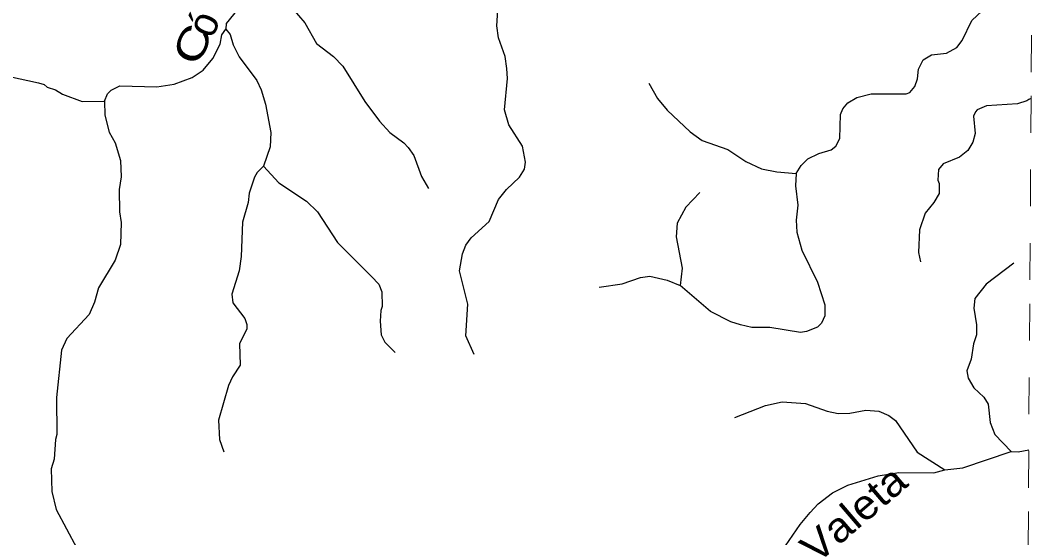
# Model space of a CAD drawing. Extents: x 577 to 602.9, y 7483.8 to 7511.6.
# Drawn here: x 600.095 to 602.863, y 7506.798 to 7508.204 of the extents above; entities that cross this region are included whole.
import ezdxf
from ezdxf.enums import TextEntityAlignment as Align

# ---------------------------------------------------------------- set-up
doc = ezdxf.new("R2010")
doc.units = 0
doc.header["$LTSCALE"] = 0.032
doc.linetypes.add('SHORT_DASHED', pattern=[2.7, 1.5, -1.2])
doc.layers.add('53', color=7, linetype='SHORT_DASHED', lineweight=13)
doc.layers.add('7', color=7, linetype='Continuous', lineweight=25)
doc.layers.add('61', color=7, linetype='Continuous')

msp = doc.modelspace()

# ---------------------------------------------------------------- linework, layer by layer
at = {"layer": '53'}
msp.add_lwpolyline([(602.7836, 7499.5909), (602.7874, 7500.1558), (602.7912, 7500.7206), (602.795, 7501.2855), (602.7988, 7501.8503), (602.8025, 7502.4151), (602.8063, 7502.98), (602.8101, 7503.5448), (602.8139, 7504.1096), (602.8177, 7504.6745), (602.8215, 7505.2393), (602.8253, 7505.8041), (602.829, 7506.369), (602.8328, 7506.9338), (602.8366, 7507.4986), (602.8404, 7508.0635), (602.8441, 7508.6283), (602.8479, 7509.1931), (602.8517, 7509.758), (602.8555, 7510.3228), (602.8592, 7510.8876), (602.863, 7511.4524)], dxfattribs=at)
at = {"layer": '7'}
for points in [[(600.7468, 7508.3628), (600.7312, 7508.3309), (600.7173, 7508.2851), (600.6969, 7508.2484), (600.6536, 7508.1952), (600.6528, 7508.1797)], [(600.7468, 7508.3628), (600.7546, 7508.3548), (600.7607, 7508.3415), (600.7721, 7508.3064), (600.7909, 7508.2704), (600.8326, 7508.2369), (600.8677, 7508.1969), (600.8988, 7508.1413), (600.9454, 7508.1053), (600.9707, 7508.0792), (601.0304, 7507.9835), (601.0705, 7507.9296), (601.0983, 7507.8993), (601.1367, 7507.8715), (601.1481, 7507.8585), (601.1637, 7507.8364), (601.1841, 7507.78), (601.2031, 7507.7474)], [(602.2018, 7507.7873), (602.2157, 7507.8094), (602.2336, 7507.8274), (602.2631, 7507.8421), (602.2966, 7507.8519), (602.3097, 7507.8617), (602.3203, 7507.883), (602.3219, 7507.9484), (602.3285, 7507.9639), (602.3424, 7507.9794), (602.3669, 7507.9941), (602.4053, 7508.004), (602.5009, 7508.004), (602.5107, 7508.008), (602.5238, 7508.0244), (602.5312, 7508.0448), (602.5344, 7508.071), (602.5467, 7508.0963), (602.5696, 7508.1102), (602.6105, 7508.1151), (602.6383, 7508.1298), (602.653, 7508.1495), (602.6791, 7508.2034), (602.7339, 7508.2549)], [(601.327, 7507.296), (601.3051, 7507.3468), (601.31, 7507.4326), (601.2871, 7507.5233), (601.2953, 7507.5691), (601.3051, 7507.5928), (601.319, 7507.6132), (601.368, 7507.6574), (601.3933, 7507.717), (601.4154, 7507.744), (601.4506, 7507.7775), (601.4636, 7507.7996), (601.4669, 7507.8184), (601.4587, 7507.8617), (601.4211, 7507.9198), (601.4097, 7507.9606), (601.4179, 7508.0456), (601.4162, 7508.0734), (601.4113, 7508.1053), (601.3933, 7508.1568), (601.3893, 7508.1887), (601.3917, 7508.232)], [(600.3234, 7507.9843), (600.3315, 7508.004), (600.3413, 7508.0138), (600.365, 7508.026), (600.4656, 7508.0228), (600.5122, 7508.0309), (600.5612, 7508.0489), (600.5915, 7508.0685), (600.6176, 7508.1004), (600.6372, 7508.1388), (600.6421, 7508.165), (600.6528, 7508.1797)], [(600.6528, 7508.1797), (600.6642, 7508.1658), (600.6724, 7508.1372), (600.6887, 7508.1045), (600.737, 7508.0407), (600.7492, 7508.0154), (600.7607, 7507.9762), (600.7754, 7507.8993), (600.7737, 7507.8601), (600.7549, 7507.8078)], [(599.9787, 7508.0644), (600.0136, 7508.0546), (600.0651, 7508.0514), (600.1443, 7508.0342), (600.1591, 7508.0293), (600.1672, 7508.0219), (600.1901, 7508.0154), (600.2089, 7508.0031), (600.2629, 7507.9835), (600.3234, 7507.9843)], [(601.8016, 7508.0333), (601.8249, 7507.9917), (601.8519, 7507.9598), (601.914, 7507.901), (601.9467, 7507.8773), (602.0162, 7507.8527), (602.0652, 7507.82), (602.1078, 7507.8004), (602.1494, 7507.7922), (602.2018, 7507.7873)], [(600.3234, 7507.9843), (600.3242, 7507.9467), (600.3356, 7507.9001), (600.352, 7507.8707), (600.3667, 7507.8233), (600.3683, 7507.7783), (600.3634, 7507.744), (600.3642, 7507.6835), (600.3683, 7507.6549), (600.3667, 7507.5944), (600.352, 7507.5519), (600.307, 7507.4767), (600.2964, 7507.4383), (600.2817, 7507.4048), (600.2212, 7507.3394), (600.2065, 7507.3075), (600.1934, 7507.1792), (600.1942, 7507.0786), (600.1901, 7507.0648), (600.1868, 7507.0116), (600.1787, 7506.9855), (600.1803, 7506.9233), (600.1918, 7506.8743), (600.2482, 7506.7697)], [(602.8399, 7507.9918), (602.8337, 7507.9884), (602.8279, 7507.9852), (602.8026, 7507.977), (602.7184, 7507.9713), (602.6938, 7507.9606), (602.6889, 7507.9549), (602.6832, 7507.9435), (602.6881, 7507.8961), (602.6816, 7507.8732), (602.6685, 7507.8503), (602.6456, 7507.8323), (602.6007, 7507.8143), (602.5884, 7507.7988), (602.5868, 7507.7694), (602.59, 7507.7604), (602.59, 7507.7334), (602.5761, 7507.7089), (602.5524, 7507.6803), (602.5369, 7507.6345), (602.5344, 7507.5732), (602.5392, 7507.5475)], [(600.7549, 7507.8078), (600.7378, 7507.7906), (600.7304, 7507.7775), (600.7165, 7507.7342), (600.7133, 7507.7089), (600.6985, 7507.6557), (600.6945, 7507.5626), (600.6887, 7507.5233), (600.6691, 7507.4596), (600.6716, 7507.4367), (600.7043, 7507.3933), (600.71, 7507.377), (600.71, 7507.3647), (600.6904, 7507.3255), (600.692, 7507.2667), (600.6708, 7507.2348), (600.6601, 7507.2119), (600.6332, 7507.1171), (600.6356, 7507.0648), (600.6475, 7507.0313)], [(600.7549, 7507.8078), (600.7966, 7507.7628), (600.8718, 7507.713), (600.9021, 7507.6835), (600.956, 7507.6002), (601.0488, 7507.5082), (601.0688, 7507.4874), (601.077, 7507.4661), (601.0778, 7507.426), (601.0737, 7507.4154), (601.0721, 7507.3868), (601.0746, 7507.3492), (601.0844, 7507.3296), (601.113, 7507.301)], [(602.2018, 7507.7873), (602.2001, 7507.7538), (602.2067, 7507.7015), (602.2018, 7507.6606), (602.2034, 7507.6279), (602.2173, 7507.5797), (602.2598, 7507.4923), (602.2794, 7507.4309), (602.2794, 7507.4007), (602.2704, 7507.3811), (602.2598, 7507.3705), (602.2295, 7507.3582), (602.214, 7507.3557), (602.1306, 7507.3696), (602.0816, 7507.3688), (602.0505, 7507.3762), (602.0244, 7507.3844), (601.9696, 7507.413), (601.8871, 7507.4833)], [(601.9401, 7507.7362), (601.9026, 7507.6966), (601.8789, 7507.6525), (601.8756, 7507.6157), (601.892, 7507.5307), (601.8871, 7507.4833)], [(602.7934, 7507.5442), (602.7175, 7507.4874), (602.6873, 7507.4481), (602.684, 7507.422), (602.6914, 7507.3762), (602.6914, 7507.3492), (602.6832, 7507.3247), (602.6767, 7507.283), (602.6652, 7507.2519), (602.6693, 7507.2315), (602.684, 7507.2053), (602.7118, 7507.18), (602.7233, 7507.1612), (602.729, 7507.1113), (602.7412, 7507.0786), (602.7854, 7507.0321)], [(601.6669, 7507.4793), (601.7293, 7507.4882), (601.7792, 7507.5053), (601.8045, 7507.5086), (601.8519, 7507.498), (601.8871, 7507.4833)], [(602.0351, 7507.1243), (602.1184, 7507.1571), (602.1642, 7507.1677), (602.2271, 7507.1628), (602.2859, 7507.1416), (602.3162, 7507.1359), (602.3473, 7507.1367), (602.3914, 7507.1449), (602.4265, 7507.1416), (602.4535, 7507.1301), (602.4715, 7507.1162), (602.5304, 7507.0304), (602.6056, 7506.9822)], [(602.6056, 7506.9822), (602.6546, 7506.9879), (602.7854, 7507.0321)], [(602.7854, 7507.0321), (602.805, 7507.0312), (602.8335, 7507.0372)], [(601.3852, 7506.6274), (601.4596, 7506.6528), (601.489, 7506.6585), (601.5609, 7506.6585), (601.6059, 7506.6626), (601.708, 7506.6879), (601.7579, 7506.6887), (601.8478, 7506.656), (601.8887, 7506.6462), (601.9524, 7506.6462), (602.0219, 7506.656), (602.0505, 7506.6659), (602.0849, 7506.6863), (602.1298, 7506.7239), (602.1731, 7506.7762), (602.2124, 7506.8342), (602.2394, 7506.8669), (602.2614, 7506.8898), (602.3007, 7506.9201), (602.3424, 7506.9405), (602.4249, 7506.9658), (602.4805, 7506.9748), (602.5761, 7506.974), (602.6056, 7506.9822)]]:
    msp.add_lwpolyline(points, dxfattribs=at)

# ---------------------------------------------------------------- texts
at = {"layer": '61'}
msp.add_text('ó', height=0.08, rotation=65.973, dxfattribs=at).set_placement((600.6278, 7508.1788), align=Align.CENTER)
for s, rotation, width, p in [('C', 65.973, 1.35, (600.5985, 7508.1227)), ('Valeta', 40.575, 1.1, (602.3837, 7506.8328))]:
    msp.add_text(s, height=0.08, rotation=rotation, dxfattribs=dict(at, width=width)).set_placement(p, align=Align.CENTER)

doc.saveas('drawing.dxf')
